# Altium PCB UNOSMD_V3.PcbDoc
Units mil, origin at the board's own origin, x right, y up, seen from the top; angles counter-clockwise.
Board outline 2700 x 2100 mil, 2 copper layers (Top, Bottom); 72 components, 62 nets, 275 pads, 97 vias.
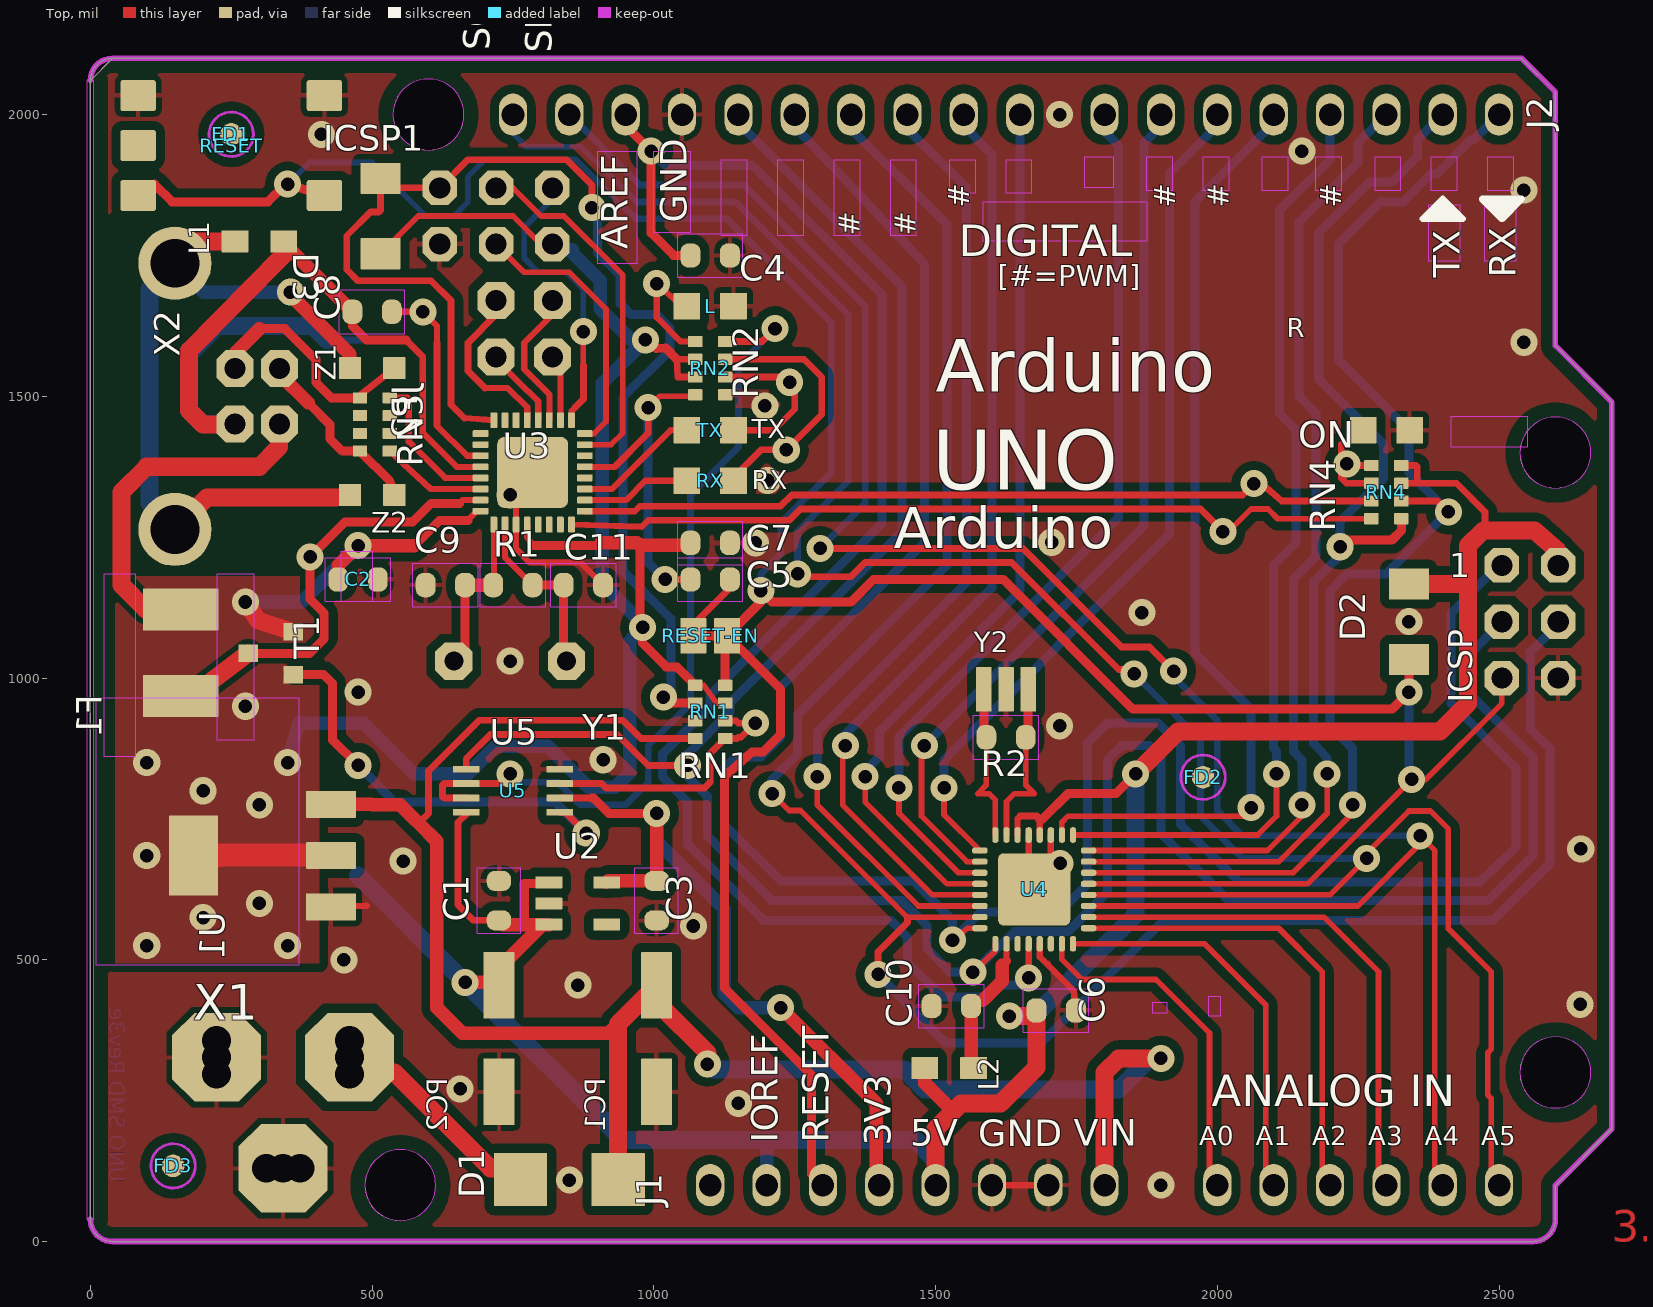
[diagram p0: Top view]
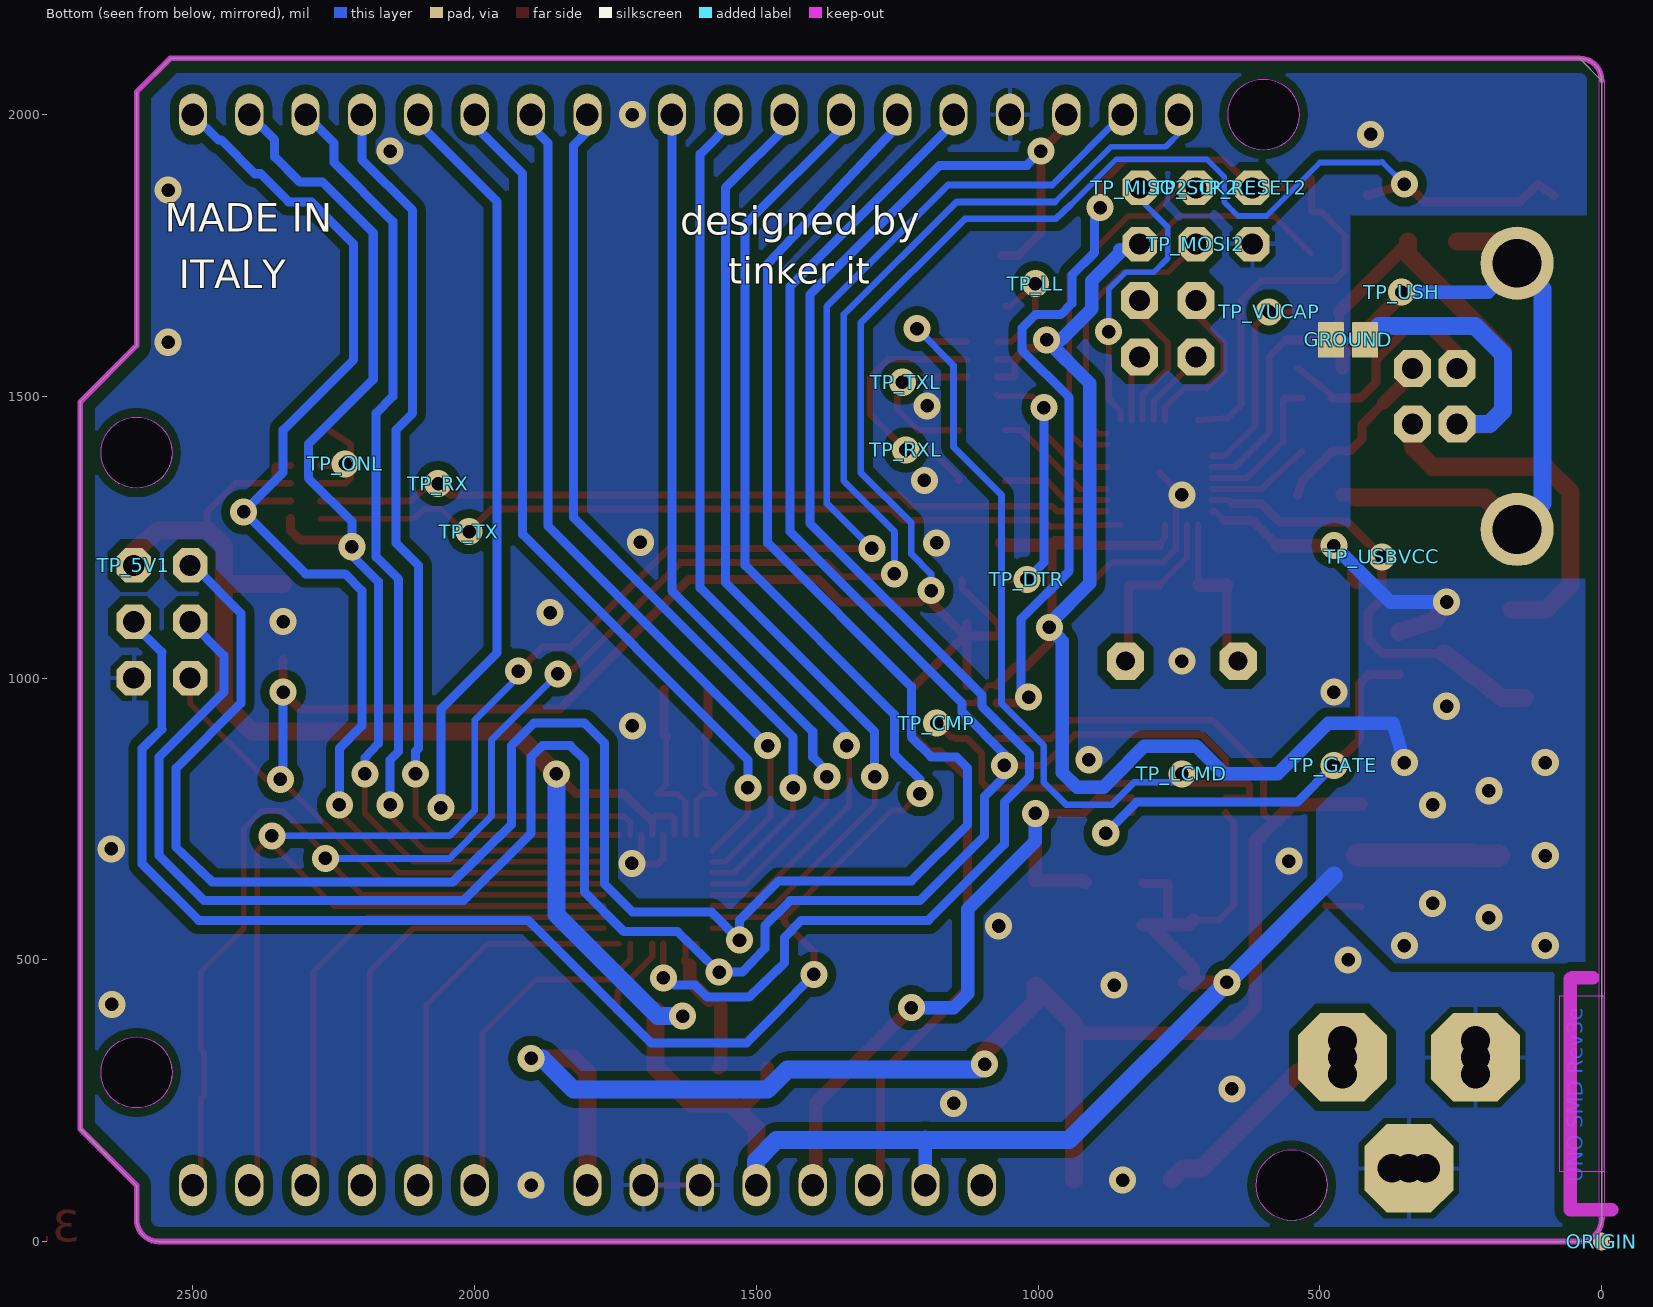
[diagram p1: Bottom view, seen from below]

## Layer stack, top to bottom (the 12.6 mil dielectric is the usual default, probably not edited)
Top Solder: solder mask 0.4, Solder Resist, Dk 3.5
Top: signal copper 1.378
Dielectric 1: dielectric 12.6, FR-4, Dk 4.8
Bottom: signal copper 1.378
Bottom Solder: solder mask 0.4, Solder Resist, Dk 3.5

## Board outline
0,2060.63 cw(c39.37,2060.63) 39.37,2100 2540,2100 2600,2040 2600,1590 2700,1490 2700,200 2600,100 2600,39.37 cw(c2560.63,39.37) 2560.63,0 39.37,0 cw(c39.37,39.37) 0,2060.63 cw(c39.37,2060.63)
cut-out: 600,1937.01 ccw(c600,2000) 662.99,2000 ccw(c600,2000) 600,2062.99 ccw(c600,2000) 537.01,2000 ccw(c600,2000)
cut-out: 550,37.01 ccw(c550,100) 612.99,100 ccw(c550,100) 550,162.99 ccw(c550,100) 487.01,100 ccw(c550,100)
cut-out: 2600,237.01 ccw(c2600,300) 2662.99,300 ccw(c2600,300) 2600,362.99 ccw(c2600,300) 2537.01,300 ccw(c2600,300)
cut-out: 2600,1337.01 ccw(c2600,1400) 2662.99,1400 ccw(c2600,1400) 2600,1462.99 ccw(c2600,1400) 2537.01,1400 ccw(c2600,1400)
cut-out: 3.83,2063.83 5.41,2060 5.41,40 3.83,36.17 0,34.59 -3.83,36.17 -5.41,40 -5.41,2060 -3.83,2063.83 0,2065.41

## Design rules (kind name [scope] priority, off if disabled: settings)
BoardOutlineClearance mdCopperDimension [All] p1: gap=10 ignorepadtopadclearanceinfootprint=FALSE except(0: Arc-SplitContinuation Track-SplitContinuation SMDPad-SplitContinuation THPad-SplitContinuation Via-SplitContinuation Fill-SplitContinuation Poly-SplitContinuation Region-SplitContinuation Text-SplitContinuation; 26: Poly-OutlineEdge Poly-CavityEdge Poly-CutoutEdge Poly-SplitBarrior)
Clearance Clearance_for_PolygonClass_Isolate_16 [InPolygonClass('Isolate_16') vs IsArc Or IsTrack Or IsPad Or IsVia Or IsFill Or IsRegion Or IsText] p1: gap=16 ignorepadtopadclearanceinfootprint=FALSE
Clearance "Clearance (Same Net)" [All] p2: gap=10 ignorepadtopadclearanceinfootprint=FALSE except(8: SMDPad-SMDPad SMDPad-THPad SMDPad-Via)
Clearance Clearance_for_NetClass_aref [InNetClass('aref') vs InNetClass('aref')] p3: gap=10 ignorepadtopadclearanceinfootprint=FALSE
Clearance Clearance_for_NetClass_usbvcc [InNetClass('usbvcc') vs InNetClass('usbvcc')] p4: gap=10 ignorepadtopadclearanceinfootprint=FALSE
Clearance Clearance_for_NetClass_gnd [InNetClass('gnd') vs InNetClass('gnd')] p5: gap=10 ignorepadtopadclearanceinfootprint=FALSE
Clearance Clearance_for_NetClass_power [InNetClass('power') vs InNetClass('power')] p6: gap=10 ignorepadtopadclearanceinfootprint=FALSE
Clearance [All] p7: gap=10 ignorepadtopadclearanceinfootprint=FALSE except(12: THPad-Via Via-Via)
HoleSize HoleSize_For_NetClass_aref [InNetClass('aref')] p1: absolutevalues=TRUE maxlimit=24 minlimit=24 maxpercent=80.000 minpercent=20.000
HoleSize HoleSize_For_NetClass_usbvcc [InNetClass('usbvcc')] p2: absolutevalues=TRUE maxlimit=24 minlimit=24 maxpercent=80.000 minpercent=20.000
HoleSize HoleSize_For_NetClass_gnd [InNetClass('gnd')] p3: absolutevalues=TRUE maxlimit=22 minlimit=22 maxpercent=80.000 minpercent=20.000
HoleSize HoleSize_For_NetClass_power [InNetClass('power')] p4: absolutevalues=TRUE maxlimit=24 minlimit=24 maxpercent=80.000 minpercent=20.000
HoleSize [All] p5: absolutevalues=TRUE maxlimit=100000 minlimit=22 maxpercent=80.000 minpercent=20.000
HoleToHoleClearance mdDrill [All] p1: gap=12 allowstackedmicrovias=TRUE
MinimumSolderMaskSliver [All] p1 off: minsoldermaskwidth=10
PasteMaskExpansion Expansion_SMDPaste_OFF [InPadClass('SMDPaste_OFF')] p1: expansion=0
PasteMaskExpansion mlMinCreamFrame [All] p2: expansion=-2
PolygonConnect PolygonConnect_For_PolygonThermal_ON_Width80000_Gap100000 [InPolygonClass('PolygonThermal_ON_Width80000_Gap100000') vs Not IsVia] p1: connectstyle=Relief reliefconductorwidth=8 reliefentries=4 polygonreliefangle="90 Angle" airgapwidth=10
PolygonConnect PolygonConnect_For_PolygonThermal_OFF [InPolygonClass('PolygonThermal_OFF')] p2: connectstyle=Direct reliefconductorwidth=10 reliefentries=4 polygonreliefangle="90 Angle" airgapwidth=10
PolygonConnect ThermalVias [IsVia] p3: connectstyle=Direct reliefconductorwidth=10 reliefentries=4 polygonreliefangle="90 Angle" airgapwidth=10
PolygonConnect [All] p4: connectstyle=Relief reliefconductorwidth=10 reliefentries=4 polygonreliefangle="90 Angle" airgapwidth=10
RoutingVias [All] p1: holewidth=22 width=46 viastyle="Through Hole" minholewidth=22 minwidth=46 maxholewidth=100 maxwidth=100
SolderMaskExpansion Expansion_SMDSolder_OFF [InPadClass('SMDSolder_OFF')] p1: expansion=0 istentingtop=FALSE
SolderMaskExpansion mlMinStopFrame [All] p2: expansion=1 istentingtop=FALSE
Width Width_For_NetClass_aref [InNetClass('aref')] p1: maxlimit=32 minlimit=10 preferedwidth=16
Width Width_For_NetClass_usbvcc [InNetClass('usbvcc')] p2: maxlimit=40 minlimit=10 preferedwidth=20
Width Width_For_NetClass_gnd [InNetClass('gnd')] p3: maxlimit=24 minlimit=10 preferedwidth=12
Width Width_For_NetClass_power [InNetClass('power')] p4: maxlimit=48 minlimit=10 preferedwidth=24
Width [All] p5: maxlimit=10000 minlimit=10 preferedwidth=10
26 further rules are at their usual default settings.

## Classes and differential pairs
polygon class PolygonThermal_ON_Width80000_Gap100000: Polygon_1_Net_GND Polygon_2_Net_GND
polygon class PolygonThermal_OFF: Polygon_1_Net_+5V Polygon_2_Net_+5V
polygon class Isolate_16: Polygon_1_Net_+5V Polygon_1_Net_GND Polygon_2_Net_GND
pad class SMDSolder_OFF: U3-1 U3-2 U3-3 U3-4 U3-5 U3-6 U3-7 U3-8 U3-9 U3-10 U3-11 U3-12 U3-13 U3-14 U3-15 U3-16 U3-17 U3-18 U3-19 U3-20 U3-21 U3-22 U3-23 U3-24 U3-25 U3-26 U3-27 U3-28 U3-29 U3-30 U3-31 U3-32 U3-EXP U4-33
pad class SMDPaste_OFF: FD1-P$1 FD2-P$1 FD3-P$1 ORIGIN-X RESET-5 TP_5V1-X TP_CMP-X TP_DTR-X TP_GATE-X TP_LCMD-X TP_LL-X TP_MISO2-X TP_MOSI2-X TP_ONL-X TP_RESET2-X TP_RX-X TP_RXL-X TP_SCK2-X TP_TX-X TP_TXL-X TP_USBVCC-X TP_USH-X TP_VUCAP-X U3-1 U3-2 U3-3 U3-4 U3-5 U3-6 U3-7 U3-8 U3-9 U3-10 U3-11 U3-12 U3-13 U3-14 U3-15 U3-16 U3-17 U3-18 U3-19 U3-20 U3-21 U3-22 U3-23 U3-24 U3-25 U3-26 U3-27 U3-28 U3-29 U3-30 U3-31 U3-32 U3-EXP U4-33
net class aref: AREF
net class usbvcc: +5V N$4 USBVCC XUSB
net class gnd: GND UGND USHIELD
net class power: PWRIN VIN

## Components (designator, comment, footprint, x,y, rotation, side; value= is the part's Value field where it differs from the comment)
C1 "100n" C0603-ROUND 725,605 r270 top
C2 "100n" C0603-ROUND 475,1175 r180 top
C3 "1u" C0603-ROUND 1005,605 r90 top
C4 "100n" C0603-ROUND 1100,1750 r180 top
C5 "100n" C0603-ROUND 1100,1175 r0 top
C6 "100n" C0603-ROUND 1714,410 r180 top
C7 "100n" C0603-ROUND 1100,1240 r0 top
C8 "1u" C0603-ROUND 500,1650 r180 top
C9 "22p" C0603-ROUND 630,1165 r180 top
C10 "100nF" C0603-ROUND 1528,418 r180 top
C11 "22p" C0603-ROUND 875,1165 r0 top
D1 "M7" SMB 850,110 r180 top
D2 "CD1206-S01575" MINIMELF 2340,1100 r270 top
D3 "CD1206-S01575" MINIMELF 515,1820 r90 top
F1 "MF-MSMF050-2 500mA" L1812 160,1045 r90 top
FD1 "" FD-1-1.5 250,1965 r0 top
FD2 "" FD-1-1.5 1974.69,824.09 r0 top
FD3 "" FD-1-1.5 146.85,134.25 r0 top
FRAME1 "" FRAME -846.46,-177.17 r0 top
GROUND "" SJ 450,1600 r180 bottom
ICSP "3x2 M" 2X03 2555,1100 r270 top
ICSP1 "3x2 M" 2X03 720,1820 r180 top
J1 "-" 1X14-CUSTOM 1800,100 r0 top
J2 "-" 1X18-CUSTOM 1800,2000 r180 top
JP2 "2x2 M-NM" 2X02 770,1620 r90 top
L "YELLOW" CHIP-LED0805 1100,1660 r270 top
L1 "BLM21" 0805 300,1775 r180 top
L2 "10uH" 0805 1524,308 r0 top
ON "GREEN" CHIP-LED0805 2300,1440 r270 top
ORIGIN "" TP-SP 0,0 r0 top
PC1 "47u" PANASONIC_D 1005,360 r90 top
PC2 "47u" PANASONIC_D 725,360 r90 top
R1 "1M" R0603-ROUND 750,1165 r0 top
R2 "1M" R0603-ROUND 1625,895 r180 top
RESET "TS42031-160R-TR-7260" TS42 250,1945 r0 top
RESET-EN "" SJ 1100,1075 r0 top
RN1 "10K" CAY16 1100,940 r90 top
RN2 "1K" CAY16 1100,1550 r270 top
RN3 "22R" CAY16 505,1450 r90 top
RN4 "1K" CAY16 2300,1330 r90 top
RX "YELLOW" CHIP-LED0805 1100,1350 r90 top
T1 "FDN340P" SOT-23 320,1045 r270 top
TP_5V1 "" TP-SP 2605,1200 r0 top
TP_CMP "" TP-SP 1180,920 r0 top
TP_DTR "" TP-SP 1020,1175 r0 top
TP_GATE "" TP-SP 475,845 r0 top
TP_LCMD "" TP-SP 745,830 r0 top
TP_LL "" TP-SP 1005,1700 r0 top
TP_MISO2 "" TP-SP 820,1870 r0 top
TP_MOSI2 "" TP-SP 720,1770 r0 top
TP_ONL "" TP-SP 2230,1380 r0 top
TP_RESET2 "" TP-SP 620,1870 r0 top
TP_RX "" TP-SP 2065,1345 r0 top
TP_RXL "" TP-SP 1235,1405 r0 top
TP_SCK2 "" TP-SP 720,1870 r0 top
TP_TX "" TP-SP 2010,1260 r0 top
TP_TXL "" TP-SP 1235,1525 r0 top
TP_USBVCC "" TP-SP 390,1215 r0 top
TP_USH "" TP-SP 355,1685 r0 top
TP_VUCAP "" TP-SP 590,1650 r0 top
TX "YELLOW" CHIP-LED0805 1100,1440 r90 top
U1 "NCP1117ST50T3G" SOT223 305,685 r90 top
U2 "LP2985-33DBVR" SOT23-DBV 865,600 r270 top
U3 "16U2" ATMEL_QFN32 785,1365 r90 top
U4 "" MLF32 1675,625 r270 top
U5 "LMV358IDGKR" MSOP08 750,800 r90 top
X1 "POWERSUPPLY_DC21MMX" POWERSUPPLY_DC-21MM 210,330 r90 top
X2 "USB-B_TH" PN61729 150,1500 r270 top
Y1 "16MHz" QS 745,1030 r180 top
Y2 "CSTCE16M0V53-R0 16MHZ" RESONATOR 1625,980 r0 top
Z1 "CG0603MLC-05E" CT/CN0603 500,1550 r180 top
Z2 "CG0603MLC-05E" CT/CN0603 500,1325 r180 top

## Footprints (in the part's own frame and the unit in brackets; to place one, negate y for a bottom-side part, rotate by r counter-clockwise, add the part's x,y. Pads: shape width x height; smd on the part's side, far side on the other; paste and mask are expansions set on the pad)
1X14-CUSTOM [mil] "1X14-CUSTOM"
  oval 50x75 hole 40: 1(-700,0) 2(-600,0) 3(-500,0) 4(-400,0) 5(-300,0) 6(-200,0) 7(-100,0) 8(0,0) 9(200,0) 10(300,0) 11(400,0) 12(500,0) 13(600,0) 14(700,0)
1X18-CUSTOM [mil] "1X18-CUSTOM"
  oval 50x75 hole 40: 1(-700,0) 2(-600,0) 3(-500,0) 4(-400,0) 5(-300,0) 6(-200,0) 7(-100,0) 8(0,0) 9(150,0) 10(250,0) 11(350,0) 12(450,0) 13(550,0) 14(650,0) 15(750,0) 16(850,0) 17(950,0) 18(1050,0)
2X02 [mil] "2X02"
  oct 66x66 / inner round 60.98 / far side oct 66x66 hole 37.4: 1(-50,-50) 2(-50,50) 3(50,-50) 4(50,50)
2X03 [mil] "2X03"
  oct 61.02x61.02 / inner round 56.38 / far side oct 61.02x61.02 hole 37.4: 1(-100,-50) 2(-100,50) 3(0,-50) 4(0,50) 5(100,-50) 6(100,50)
0805 [mm] "0805"
  rrect5% 1.2x1 smd: 1(-1.1,0) 2(1.1,0)
ATMEL_QFN32 [mil] "ATMEL_QFN32"
  rrect30% 28x12 smd paste-14 mask-14: 1(-92.55,68.9) 2(-92.55,49.21) 3(-92.55,29.53) 4(-92.55,9.84) 5(-92.55,-9.84) 6(-92.55,-29.53) 7(-92.55,-49.21) 8(-92.55,-68.9) 17(92.55,-68.9) 18(92.55,-49.21) 19(92.55,-29.53) 20(92.55,-9.84) 21(92.55,9.84) 22(92.55,29.53) 23(92.55,49.21) 24(92.55,68.9)
  rrect30% 12x28 smd paste-14 mask-14: 9(-68.9,-92.55) 10(-49.21,-92.55) 11(-29.53,-92.55) 12(-9.84,-92.55) 13(9.84,-92.55) 14(29.53,-92.55) 15(49.21,-92.55) 16(68.9,-92.55) 25(68.9,92.55) 26(49.21,92.55) 27(29.53,92.55) 28(9.84,92.55) 29(-9.84,92.55) 30(-29.53,92.55) 31(-49.21,92.55) 32(-68.9,92.55)
  rrect20% 125.98x125.98 smd paste-62.99 mask-62.99: EXP(0,0)
C0603-ROUND [mil] "C0603-ROUND"
  rrect80% 35.37x43.31 smd: 1(-35,0) 2(35,0)
  Top keep-out lines w2: 57.99,-38.7 -57.99,-38.7 -57.99,38.7 57.99,38.7 57.99,-38.7
CAY16 [mm] "CAY16"
  rrect10% 0.5x0.65 smd: 1(-1.2,-0.675) 2(-0.4,-0.675) 3(0.4,-0.675) 4(1.2,-0.675) 5(1.2,0.675) 6(0.4,0.675) 7(-0.4,0.675) 8(-1.2,0.675)
CHIP-LED0805 [mil] "CHIP-LED0805"
  rrect4% 47.24x47.24 smd: A(0,-41.34) C(0,41.34)
CT/CN0603 [mm] "CT/CN0603"
  rrect5% 1x1 smd: 1(-1,0) 2(1,0)
FD-1-1.5 [mil] "FD-1-1.5"
  rrect100% 40x40 smd paste-20: P$1(0,0)
  Top keep-out circle w5: c0,0 r39.37
FRAME [mil] "FRAME"
L1812 [mil] "L1812"
  rrect2% 74.8x133.86 smd: 1(-76.77,0) 2(76.77,0)
MINIMELF [mil] "MINIMELF"
  rrect3% 55.12x70.87 smd: A(66.93,0) C(-66.93,0)
MLF32 [mil] "MLF32"
  rrect80% 27.56x11.02 smd: 1(-96.46,68.9) 2(-96.46,49.21) 3(-96.46,29.53) 4(-96.46,9.84) 5(-96.46,-9.84) 6(-96.46,-29.53) 7(-96.46,-49.21) 8(-96.46,-68.9) 17(96.46,-68.9) 18(96.46,-49.21) 19(96.46,-29.53) 20(96.46,-9.84) 21(96.46,9.84) 22(96.46,29.53) 23(96.46,49.21) 24(96.46,68.9)
  rrect80% 11.02x27.56 smd: 9(-68.9,-96.46) 10(-49.21,-96.46) 11(-29.53,-96.46) 12(-9.84,-96.46) 13(9.84,-96.46) 14(29.53,-96.46) 15(49.21,-96.46) 16(68.9,-96.46) 25(68.9,96.46) 26(49.21,96.46) 27(29.53,96.46) 28(9.84,96.46) 29(-9.84,96.46) 30(-29.53,96.46) 31(-49.21,96.46) 32(-68.9,96.46)
  rrect15% 128.11x128.11 smd paste-64.06 mask-64.06: 33(0,0)
MSOP08 [mil] "MSOP08"
  rrect16% 11.81x47.24 smd: 1(-38.43,-83.19) 2(-12.83,-83.19) 3(12.76,-83.19) 4(38.35,-83.19) 5(38.35,83.15) 6(12.76,83.15) 7(-12.83,83.15) 8(-38.43,83.15)
PANASONIC_D [mm] "PANASONIC_D"
  rrect3% 3x1.4 smd: +(2.4,0) -(-2.4,0)
PN61729 [mil] "PN61729"
  oct 66x66 / inner round 60.98 / far side oct 66x66 hole 37.4: 1(49.21,185.43) 2(-49.21,185.43) 3(-49.21,106.69) 4(49.21,106.69)
  round 129.91 hole 86.61: P$1(-236.22,0) P$2(236.22,0)
POWERSUPPLY_DC-21MM [mil] "POWERSUPPLY_DC-21MM"
  oct 157.48x157.48 / inner round 145.49 / far side oct 157.48x157.48 hole 51.18: 1(-200,-132) 2(-3,-250) 3(-3,-14)
  round 76.77 hole 51.18: 4(-200,-162) 5(-200,-102) 6(-33,-14) 7(27,-14) 8(-33,-250) 9(27,-250)
QS [mil] "QS"
  oct 66x66 / inner round 60.98 / far side oct 66x66 hole 33.46: 1(-100,0) 2(100,0)
R0603-ROUND [mil] "R0603-ROUND"
  rrect80% 35.37x43.31 smd: 1(-35,0) 2(35,0)
  Top keep-out lines w2: -57.99,-38.7 -57.99,38.7 57.99,38.7 57.99,-38.7 -57.99,-38.7
RESONATOR [mm] "RESONATOR"
  rrect7% 0.7x2 smd: 1(-1,0) 2(0,0) 3(1,0)
SJ [mil] "SJ"
  rrect4% 46x63 smd: 1(-30,0) 2(30,0)
SMB [mil] "SMB"
  rrect2% 94.49x94.49 smd: A(86.61,0) C(-86.61,0)
SOT23-DBV [mil] "SOT23-DBV"
  rrect9% 21.65x47.24 smd: 1(-37.4,-51.18) 2(0,-51.18) 3(37.4,-51.18) 4(37.4,51.18) 5(-37.4,51.18)
SOT223 [mil] "SOT223"
  rrect4% 48x88 smd: 1(-91,-122) 2(0,-122) 3(91,-122)
  rrect2% 141.73x86.61 smd: 4(0,122.01)
SOT-23 [mil] "SOT-23"
  rrect6% 31x35 smd: 1(1,-40) 2(-37,40) 3(39,40)
TP-SP [mil] "TP-SP"
  rrect100% 31.5x31.5 smd far side paste-15.75: X(0,0)
TS42 [mil] "TS42"
  rrect15% 62.99x55.12 smd: 1(-165.35,88.58) 2(165.35,88.58) 3(-165.35,-88.58) 4(165.35,-88.58)
  rrect15% 62.99x55.12 smd paste-31.5: 5(-165.35,0)

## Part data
C1 C2 C3 C4 C5 C6 C7 C8 C9 C10 C11: library part C0603-ROUND
D1: library part SMB
D2 D3: library part MINIMELF
F1: library part L1812
FD1 FD2 FD3: library part FD-1-1.5
FRAME1: library part FRAME
GROUND RESET-EN: library part SJ
ICSP ICSP1: library part 2X03
J1: library part 1X14-CUSTOM
J2: library part 1X18-CUSTOM
JP2: library part 2X02
L ON RX TX: library part CHIP-LED0805
L1 L2: library part 0805
ORIGIN TP_5V1 TP_CMP TP_DTR TP_GATE TP_LCMD TP_LL TP_MISO2 TP_MOSI2 TP_ONL TP_RESET2 TP_RX TP_RXL TP_SCK2 TP_TX TP_TXL TP_USBVCC TP_USH TP_VUCAP: library part TP-SP
PC1 PC2: library part PANASONIC_D
R1 R2: library part R0603-ROUND
RESET: library part TS42
RN1 RN2 RN3 RN4: library part CAY16
T1: library part SOT-23
U1: library part SOT223
U2: library part SOT23-DBV
U3: library part ATMEL_QFN32
U4: library part MLF32
U5: library part MSOP08
X1: library part POWERSUPPLY_DC-21MM
X2: library part PN61729
Y1: library part QS
Y2: library part RESONATOR
Z1 Z2: library part CT/CN0603

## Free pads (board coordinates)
  round 125.98 hole 125.98 unplated: MH1(2600,1400) MH2(2600,300) MH3(600,2000) MH4(550,100)

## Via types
v1: diameter 48/48 (per signal layer), hole 24, Top to Bottom, 97 vias

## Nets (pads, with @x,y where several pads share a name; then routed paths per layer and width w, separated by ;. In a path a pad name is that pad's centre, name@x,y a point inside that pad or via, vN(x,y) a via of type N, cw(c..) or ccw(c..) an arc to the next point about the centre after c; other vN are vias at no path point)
5-GND: RESET.5
+3V3: C3.2 J1.4 U2.5 U5.2 | length 1260.5
  Top w12: U5.2 890.2,787.17
  Top w16: 890.2,787.17 892.83,787.17 920,760 v1(1005,760)
  Top w24: U2.5 918.78,640 C3.2 v1(1005,760) ; v1(1225,415) 1395,245 1395,105 J1.4
  Bottom w24: v1(1005,760) 1005,710 1125,590 1125,440 1150,415 v1(1225,415)
+5V: C1.2 C2.2 C6.2 C7.1 D2.C D3.C ICSP1.2 ICSP.2 J1.2 J1.5 L2.1 PC2.+ RN1.3 RN1.5 RN2.2 RN2.3 RN4.3 RN4.4 T1.2 TP_5V1.X U1.2 U1.4 U2.1 U2.3 U3.4 U3.32 U4.4 U4.6 U5.8 | length 9012.6
  Top w10: D3.C 581.93,1820 750,1820 800,1770 ICSP1.2 ; RN1.5@1075.67,985 RN1.5 1088.76,987.24 1111.25,955.75 RN1.3
  Top w11: 670,1280 686.1,1296.1 U3.32 ; U3.4 775.16,1249.84 785,1235 ; U4.6 1645.47,750.47 1650,755 ; U4.4 1684.84,750.16
  Top w12: U5.8 668.43,760 652.5,744.07 652.5,597.5 680,570 C1.2 ; RN2.3 1042.24,1534.25 1040.75,1565.75 RN2.2 ; 1650,755 1680,755 1684.84,750.16 ; RN4.3 2355,1345.75 ; RN4.4 2352.76,1377.24 2355,1375 2355,1345.75 ; 2475,1262 2475,1295 2424.25,1345.75 2355,1345.75
  Top w16: 575,1235 620,1280 670,1280 ; 770,562.6 770,635 811.42,635 U2.1 ; 785,1235 901.07,1235 906.61,1240.54 ; 975,1235.54 975,1110 v1(980,1090) 980,1061.93 1021.93,1020 1040.67,1020 RN1.5 ; v1(985,1600) 1005,1585 1020.75,1585.75 1040.75,1565.75 ; 1684.84,750.16 1690.16,750.16 1735,795 1820,795 v1(1855,830)
  Top w20: U1.2 U1.2@434,686 ; ICSP.2@2600,1200 ICSP.2
  Top w24: C2.2@435,1170 C2.2 440,1200 v1(475,1235) 575,1235 ; v1(665,460) PC2.+@725,460 ; C1.2 732.4,562.6 770,562.6 U2.3@802.6,562.6 ; U2.3 U2.3@802.6,562.6 ; 906.61,1240.54 970,1240.54 975,1235.54 1060.54,1235.54 C7.1 ; L2.1 1480.69,281.31 1531,231 ; PC2.+@725,460 725,485 U2.3@802.6,562.6 ; PC2.+@725,460 PC2.+ 739.49,460 PC2.+@725,460
  Top w32: v1(275,1135) 298,1102 T1.2 ; J1.5 1500,200 1531,231 1545,245 1615,245 1679,309 C6.2 1669,400 v1(1631,400) ; v1(1855,830) 1930,905 2395,905 2445,955 2445,1160 ; D2.C 2438.07,1166.93 2445,1160 ; ICSP.2@2605,1198.54 ICSP.2 2605,1225 2563,1262 2475,1262 2472,1262 2445,1235 2445,1160
  Top w40: U1.4 230,685 231,686 U1.2@434,686
  Bottom w24: v1(275,1135) 375,1135 v1(475,1235) ; v1(350,850) 370,920 485,920 575,830 670,830 719,879 812,879 841,850 840,850 884,806 931,806 957,832 957,1065 v1(980,1090) 980,1096.6 908.3,1168.3 908.3,1523.3 v1(985,1600) 960,1600 905,1655 905,1705 855,1755 855,1760 830,1760 ICSP1.2 ; J1.2 1200,180 1200,185 1205,180
  Bottom w32: 475,650 v1(665,460) 945,180 1200,180 1205,180 1464,180 1501,143 J1.5 ; v1(1631,400) 1675,400 1855,580 v1(1855,830)
  other v1: 100,525 350,525 200,575 300,600 100,685 300,775 200,800 100,850 275,950
A0: J1.9 U4.23 | length 618.5
  Top w10: U4.23 1724.21,500.79 1760,465 1891,465 1986,370 1986,118 J1.9
A1: J1.10 U4.24 | length 711.9
  Top w10: U4.24 1977.46,528.54 2086,420 2086,118 J1.10
A2: J1.11 U4.25 | length 830.3
  Top w10: U4.25 2108.9,556.1 2186,479 2186,118 J1.11
A3: J1.12 U4.26 | length 938.4
  Top w10: U4.26 2189.21,575.79 2286,479 2286,118 J1.12
A4/SDA: J1.13 J2.17 U4.27 | length 3796.6
  Top w10: U4.27 2249.47,595.47 2360,706 v1(2360,720) 2386,694 2386,118 J1.13
  Top w12: v1(1295,1230) 1655,1230 1830,1055 1880,1055 v1(1922.5,1012.5) v1@1930,1010
  Bottom w12: J2.17 975,1875 1160,1875 1375,1660 1375,1310 v1(1295,1230) ; v1(1922.5,1012.5) 1925,1010 1925,1000 2000,925 2000,765 2045,720 v1(2360,720)
A5/SCL: J1.14 J2.18 U4.28 | length 3974.1
  Top w10: U4.28 2200.16,615.16 v1(2265,680) 2272,687 2272,696 2340,764 2378,764 2410,732 2410,555 2486,479 2486,341 2480,335 2480,260 2486,254 2486,118 J1.14
  Top w12: v1(1255,1185) 1255,1180 1350,1180 1375,1205 1635,1205 1825,1015 1845,1015 v1(1852.5,1007.5)
  Bottom w10: J2.18 748.03,1998.03 748.03,1968.5 773.54,1943 871,1943 970,1845
  Bottom w12: 970,1845 1145,1845 1345,1645 1345,1350 1255,1260 v1(1255,1185) ; v1(1852.5,1007.5) 1970,890 1970,755 2045,680 v1(2265,680)
AREF: C4.2 J2.16 U4.20 | length 2810.4
  Top w10: J2.16@940,1990 J2.16
  Top w11: v1@1665.16,475.16 U4.20
  Top w12: v1(1665,468) v1@1665.16,475.16
  Top w16: J2.16@940,1990 v1(995,1935) 995,1790 1035,1750 C4.2
  Bottom w16: v1(995,1935) 1020,1910 1175,1910 1405,1680 1405,1275 1100,970 1100,950 1015,865 1015,825 1060,780 1060,705 1195,570 1420,570 1450,540 1450,495 1513,434 1588,434 1609,455 1645,455 v1(1665,468)
CMP: RN1.1 RN1.2 TP_CMP.X U5.3 | length 482.8
  Top w12: U5.3 907.24,812.76 915,805 1090,805 1100,815 1100,866.18 RN1.1 1147.76,892.76 1150,895 1155,895 v1(1180,920) 1150,920 1145.75,924.25 RN1.2
D+: RN3.5 X2.3 Z1.1 | length 426.7
  Top w12: RN3.5 476.18,1500 Z1.1
  Top w16: 300,1620 345,1620 400,1565 400,1525 427.76,1497.24 RN3.5
  Top w24: X2.3 256.69,1576.69 300,1620
  Bottom w24: X2.3@255.91,1550 X2.3
D-: RN3.8 X2.2 Z2.1 | length 325.3
  Top w16: 386.54,1488.46 425,1450 425,1425 447.24,1402.76 RN3.8 531.18,1350 Z2.1
  Top w24: X2.2 335.79,1539.21 386.54,1488.46
  Bottom w12: X2.2@335,1549.65 X2.2
DTR: C5.1 RN2.4 TP_DTR.X U3.13 | length 637.7
  Top w10: v1(990,1480) 1010,1500 RN2.4@1070.67,1500
  Top w11: U3.13 929.84,1374.84
  Top w12: 929.84,1374.84 990,1435 v1(990,1480) ; v1(1020,1175) C5.1 ; RN2.4@1070.67,1500 RN2.4
  Bottom w16: v1(990,1480) 990,1205 v1(1020,1175)
GATE_CMD: T1.3 TP_GATE.X U5.1 | length 756.9
  Top w12: U5.1 843.43,761.57 v1(880,725)
  Top w16: T1.3 414,1006 430,990 430,890 v1(475,845)
  Bottom w16: v1(475,845) 540,780 825,780 v1(880,725)
GND: C1.1 C2.1 C3.1 C4.1 C6.1 C7.2 C9.2 C10.2 C11.2 GROUND.1 ICSP1.6 ICSP.6 J1.6 J1.7 J2.15 L.C ON.C PC1.- PC2.- RESET.1 RESET.2 RN1.7 RN2.5 U1.1 U2.2 U3.3 U3.EXP U4.3 U4.5 U4.21 U5.4 X1.1 X1.3 X1.4 X1.5 X1.6 X1.7 Y2.2 | length 870.4
  Top w11: v1(745,1325) 755.47,1314.53 U3.3 755.47,1229.53 780,1205 870,1205 C11.2 ; 1665.16,679.84 U4.5 ; U4.21 1684.84,505.16 1745,445 ; v1@1704.53,687.47 U4.3
  Top w12: U1.1 490,596 ; U3.EXP@755.47,1319.53 v1(745,1325) U3.EXP ; J1.6 J1.7 ; 1665.16,679.84 1675,670 1720,670 v1(1721,671) v1@1704.53,687.47 ; 1745,445 C6.1
  Bottom w12: 425,1600 GROUND.1
  other v1: 1900,100 850,109 1150,245 656,271 2644,421 865,455 450,500 1070,560 555,675 2645,697 910,855 1720,915 475,975 745,1030 2340,1100 1866,1116 1180,1240 1706,1241 1202,1351 1197,1483 2544,1596 2544,1866 2150,1935 410,1965 1720,2000
IO0: J2.1 RN4.2 U4.30 | length 2219.2
  Top w10: U4.30 2134.53,654.53 2240,760 v1(2240,775)
  Top w12: RN4.2 2390.75,1314.25 v1(2410,1295)
  Bottom w16: v1(2240,775) 2240,875 2200,915 2200,1155 2230,1185 2300,1185 v1(2410,1295) 2340,1365 2340,1440 2215,1565 2215,1770 2290,1845 2330,1845 2380,1895 2390,1895 2450,1955 2455,1955 J2.1
IO1: J2.2 RN4.1 U4.31 | length 2064.7
  Top w10: U4.31 2109.21,674.21 2195,760 v1(2195,830)
  Top w16: v1(2218,1233) 2230,1245 2310,1245 2326.57,1261.57 RN4.1
  Bottom w16: v1(2195,830) 2195,858 2171,884 2171,1171 2220,1220 2220,1225 v1(2218,1233) 2218,1278 2295,1355 2295,1415 2180,1530 2180,1790 2270,1880 2310,1880 2355,1925 2355,1955 J2.2
IO2: J2.3 U4.32 | length 1748.3
  Top w10: U4.32 2088.9,693.9 2150,755 v1(2150,775)
  Bottom w16: v1(2150,775) 2150,855 2135,870 2135,1175 2175,1215 2175,1470 2145,1500 2145,1810 2250,1915 2250,1950 J2.3
IO3: J2.4 U4.1 | length 1688.3
  Top w10: U4.1 2071.46,721.46 2105,755 v1(2105,830)
  Bottom w16: v1(2105,830) 2105,870 2100,875 2100,1200 2140,1240 2140,1440 2110,1470 2110,1830 2200,1920 J2.4
IO4: J2.5 U4.2 | length 1697.2
  Top w10: U4.2 1724.21,744.21 1735,755 2045,755 v1(2060,770)
  Bottom w16: v1(2060,770) 2060,945 1960,1045 1960,1845 2095,1980 J2.5
IO5: J2.6 U4.9 | length 1533.3
  Top w10: v1(1515,805) 1515,757.44 U4.9
  Bottom w16: v1(1515,805) 1515,855 1915,1255 1915,1895 2000,1980 J2.6
IO6: J2.7 U4.10 | length 1558
  Top w10: v1(1480,880) 1475,875 1475,755 1555.79,674.21 U4.10
  Bottom w16: v1(1480,880) 1870,1270 1870,1950 1900,1980 J2.7
IO7: J2.8 U4.11 | length 1599.1
  Top w10: v1(1435,805) 1435,760 1540.47,654.53 U4.11
  Bottom w16: v1(1435,805) 1435,895 1825,1285 1825,1945 1800,1970 J2.8
IO8: J2.9 U4.12 | length 1597.6
  Top w10: v1(1375,825) 1375,780 1520.16,634.84 U4.12
  Bottom w10: J2.9@1650,1990 J2.9
  Bottom w16: v1(1375,825) 1375,835 1400,860 1400,905 1650,1155 J2.9@1650,1990
IO9: J2.10 U4.13 | length 1673.5
  Top w10: v1(1340,880) 1340,875 1335,870 1335,775 1494.84,615.16 U4.13
  Bottom w10: J2.10@1540,1990 J2.10
  Bottom w16: v1(1340,880) 1340,900 1600,1160 1600,1930 J2.10@1540,1990
L13: RN2.8 TP_LCMD.X U5.6 U5.7 | length 1471.7
  Top w12: U5.7 627.83,787.17 625,790 625,810 627.76,812.76 U5.6 727.76,812.76 v1(745,830) ; RN2.8 1192.24,1597.24 v1(1215,1620)
  Bottom w12: v1(745,830) 760,815 830,815 870,775 950,775 990,815 990,880 1065,955 1065,1325 1150,1410 1150,1555 v1(1215,1620)
M8RXD: RN4.7 TP_RX.X U3.9 | length 1427.5
  Top w11: U3.9 966.1,1296.1 975,1305
  Top w12: 975,1305 1225,1305 1245,1325 2045,1325 v1(2065,1345) 2078.5,1345 2114.25,1314.25 RN4.7
M8TXD: RN4.8 TP_TX.X U3.8 | length 1472.9
  Top w10: v1(2010,1260) 2020,1260 2060,1300 2090,1300 2107.24,1282.76 RN4.8
  Top w11: U3.8 978.54,1268.54 990,1280
  Top w12: 990,1280 1240,1280 1260,1300 1970,1300 v1(2010,1260)
MISO: ICSP.1 J2.13 U4.16 | length 4215.7
  Top w10: v1(1530,535) 1556.1,556.1 U4.16
  Bottom w10: J2.13@1240,1990 J2.13
  Bottom w16: J2.13@1240,1990 1480,1735 1480,1240 1225,985 1225,895 1190,860 1145,860 1125,840 1125,740 1225,640 1460,640 1530,570 v1(1530,535) 1580,585 1720,585 1770,635 1770,885 1805,920 1895,920 1935,880 1935,740 2039,638 2466,638 2530,700 2530,840 2415,955 2415,1115 2498.03,1198.03 ICSP.1
MISO2: ICSP1.1 TP_MISO2.X U3.17 | length 514.7
  Top w10: 875,1555 v1(875,1615)
  Top w11: U3.17 853.9,1473.9 860,1480
  Top w12: 860,1480 875,1495 875,1555
  Bottom w10: ICSP1.1 820,1850 770,1800 770,1745 795,1720 845,1720 875,1690 v1(875,1615)
MOSI: ICSP.4 J2.12 U4.15 | length 3836
  Top w10: v1(1210,795) 1240,765 1260,765 1449.21,575.79 ; 1450,575 1449.21,575.79 ; U4.15 1449.21,575.79
  Top w12: v1(1398,474) 1398,514 1450,566 1450,575
  Bottom w10: J2.12@1340,1985 1340,1990 J2.12
  Bottom w15: 2555,909 2555,1046
  Bottom w16: v1(1210,795) 1210,820 1255,865 1255,935 1520,1200 1520,1805 J2.12@1340,1985 ; v1(1398,474) 1465,405 1518,352 1687,352 1905,570 2490,570 2590,670 2590,875 2555,909 ; 2555,1046 2605.51,1095.51 ICSP.4
MOSI2: ICSP1.4 TP_MOSI2.X U3.16 | length 488.8
  Top w10: ICSP1.4 770,1720 850,1720 915,1655 915,1455 893.9,1433.9 U3.16
N$1: L.A RN2.1 TP_LL.X | length 215
  Top w11: L.A 1050,1660 v1(1005,1700) 1005,1640 1047.76,1597.24 RN2.1
N$3: ON.A RN4.5 RN4.6 TP_ONL.X | length 221.2
  Top w12: ON.A 2220,1415 v1@2220,1390 ; RN4.6 2229.25,1345.75 2220,1355 v1@2220,1390 ; RN4.5 2242.76,1377.24 v1(2230,1380) v1@2220,1390
N$4: C10.1 L2.2 U4.18 | length 254.8
  Top w10: 1625.79,497.79 U4.18
  Top w16: C10.1 1573,428 1584,428 ; 1618,490 1625.79,497.79
  Top w24: C10.1 1563,312.31 L2.2 ; 1584,428 1618,462 1618,490
N$35: RN2.7 RX.A TP_RXL.X | length 461.7
  Top w12: RN2.7 1266.25,1565.75 1298,1534 1298,1468 v1(1235,1405) 1190,1405 1140,1355 1140,1350 RX.A
N$36: RN2.6 TP_TXL.X TX.A | length 297.6
  Top w12: RN2.6 1225.75,1534.25 v1(1241,1525) 1250,1510 1250,1477 1212.76,1439.76 1151.57,1439.76 TX.A
  Bottom w16: TP_TXL.X v1(1241,1525)
PB4: JP2.1 U3.18 | length 118.3
  Top w11: U3.18 JP2.1@834.21,1555.79
  Top w12: JP2.1 JP2.1@834.21,1555.79
PB5: JP2.3 U3.19 | length 251.6
  Top w11: U3.19 814.53,1503.47 770,1548 770,1595 JP2.3@820,1645
  Top w12: JP2.3@820,1645 JP2.3
PB6: JP2.2 U3.20 | length 144
  Top w11: JP2.2 720,1564 794.84,1491.16 U3.20
PB7: JP2.4 U3.21 | length 300.4
  Top w11: 700,1515 740,1515 775.16,1480.84 U3.21
  Top w12: 700,1515 670,1545 670,1595 720,1645 JP2.4
PWRIN: D1.A X1.2 X1.8 X1.9 | length 396.1
  Top w32: X1.2 487,300 540,300 710,130 743.39,130 D1.A
  Bottom w32: X1.2 X1.9@462,325
RD+: RN3.4 U3.29 | length 263.7
  Top w11: 565,1420 629.84,1355.16 U3.29
  Top w12: RN3.4 562.76,1497.24 565,1495 565,1420
RD-: RN3.1 U3.30 | length 188.5
  Top w10: RN3.1 RN3.1@532.72,1402.76
  Top w11: RN3.1 603.86,1335.47 U3.30
RESET: C5.2 D2.A ICSP.5 J1.3 RESET-EN.1 RESET-EN.2 RESET.3 RESET.4 RN1.4 U4.29 | length 6074.7
  Top w10: U4.29 2159.84,634.84 v1(2345,820) 2370,820 2505,955 ICSP.5
  Top w12: RESET-EN.1 1070,1095 1135,1160 C5.2
  Top w16: RESET.3 113.58,1876.42 145,1845 315,1845 345,1875 v1(350,1876.42) RESET.4 ; RESET-EN.1 RESET-EN.2@1126.57,1075 ; RN1.4 RESET-EN.2@1126.57,1075 ; J1.3 1280,120 1280,295 1125,450 1125,825 1174,869 1194,869 1225,900 1225,980 RESET-EN.2 ; D2.A v1(2340,975) 2310,945 1850,945 1620,1175 1390,1175 1350,1135 1210,1135 v1(1190,1155) 1190,1135 RESET-EN.2 ; RESET-EN.2@1126.57,1075 1126.57,1096.57 RESET-EN.2 ; RESET-EN.2@1126.57,1075 RESET-EN.2
  Bottom w10: v1(350,1876.42) 389.58,1916 395.58,1915 500,1915 595,1820 645,1820 670,1845 670,1890 701,1921 861,1921 942,1840
  Bottom w12: 942,1840 969,1815 1130,1815 1315,1630 1315,1365 1225,1275 1225,1220 1190,1185 v1(1190,1155)
  Bottom w16: v1(2340,975) 2340,825 v1(2345,820)
RESET2: D3.A ICSP1.5 RN1.6 TP_RESET2.X U3.24 | length 2224.8
  Top w11: 663.54,1461.46 U3.24
  Top w12: 663.54,1461.46 640,1485 640,1670 605,1705 475,1705 455,1725 455,1785 496.93,1826.93 511.93,1826.93 515,1830 D3.A 531.93,1870 ICSP1.5 670,1920 845,1920 890,1875 v1(890,1835)
  Top w16: v1(1017,966) 1017.25,965.75 1030,955 1030.75,955.75 RN1.6
  Bottom w16: v1(890,1835) 900,1825 900,1755 940,1715 940,1665 960,1645 1005,1645 1029,1621 1029,1582 945,1498 945,1190 1030,1105 1030,979 v1(1017,966)
RXLED: RX.C U3.10 | length 195.3
  Top w11: U3.10 950.79,1315.79 985,1350 RX.C
SCK: ICSP.3 J2.14 U4.17 U5.5 | length 4709.8
  Top w10: v1(1566,478) 1606.1,516.1 U4.17
  Top w12: U5.5 666.85,856.85 710,900 935,900 990,845 v1(1060,845)
  Bottom w10: J2.14@1140,1995 1145,1995 J2.14
  Bottom w16: J2.14@1140,1995 1440,1695 1440,1260 1135,955 1135,940 1060,865 v1(1060,845) 1060,825 1095,790 1095,720 1210,605 1440,605 1485,560 1485,520 1525,478 v1(1566,478) 1640,550 1735,550 1805,620 1805,855 1830,880 1880,880 1900,860 1900,725 2020,605 2480,605 2560,685 2560,860 2445,975 2445,1040 ICSP.3
SCK2: ICSP1.3 TP_SCK2.X U3.15 | length 645.3
  Top w10: ICSP1.3 750,1870 800,1820 840,1820 945,1715 945,1435 924.21,1414.21 U3.15
SS: J2.11 U4.14 | length 1749.4
  Top w10: v1(1290,825) 1290,775 1469.53,595.47 U4.14
  Bottom w10: J2.11@1440,1985 1440,1990 J2.11
  Bottom w16: v1(1290,825) 1290,905 1555,1170 1555,1870 J2.11@1440,1985
TP_VUCAP: C8.1 TP_VUCAP.X U3.27 | length 367
  Top w11: C8.1 v1(590,1650) 615,1625 615,1595 ; 615,1448 668.47,1394.53 U3.27
  Top w12: 615,1448 615,1595
TXLED: TX.C U3.11 | length 224.4
  Top w11: U3.11 925.47,1335.47 1030,1440 TX.C
UGND: C8.2 GROUND.2 L1.1 U3.28 X2.4 | length 1541.4
  Top w11: 590,1435 650.16,1374.84 U3.28
  Top w12: 560,1600 590,1570 590,1435
  Top w16: C8.2 465,1625 490,1600 560,1600
  Top w24: L1.1 343.31,1771.69 343.46,1771.54 C8.2
  Top w32: X2.4 255.91,1450 200,1450 175,1475 175,1581 344.31,1752.31 343.46,1771.54 L1.1
  Bottom w24: X2.4@255.91,1450 X2.4
  Bottom w32: X2.4 199.21,1450.79 175,1475 175,1575 225,1625 395,1625 GROUND.2
USBVCC: F1.1 T1.1 TP_USBVCC.X U3.31 | length 838.6
  Top w11: 655,1310 660.79,1315.79 U3.31
  Top w16: T1.1 389,1044 415,1070 415,1115 390,1140 v1(390,1215) 452,1277 572,1277 605,1310 655,1310
  Top w24: F1.1@136.77,965 F1.1
  Top w32: F1.1@136.77,965 176,965 T1.1
USHIELD: L1.2 TP_USH.X X2.P$1 X2.P$2 Z1.2 Z2.2 | length 1373.4
  Top w24: v1(355,1685) 355,1680 460.63,1574.37 Z1.2 ; 435.63,1320.63 440.63,1320.63 445,1325 Z2.2
  Top w32: X2.P$2 206.85,1320.63 435.63,1320.63 ; X2.P$1 188.78,1775 L1.2
  Bottom w24: X2.P$1 201.22,1685 v1(355,1685)
  Bottom w32: X2.P$2 150,1265 105,1310 105,1690 150,1735 X2.P$1
VIN: D1.C J1.8 PC1.+ RN1.8 U1.3 | length 3250.1
  Top w12: 582.5,742.5 600,760 600,835 690,925 945,925 977.24,892.76 RN1.8
  Top w24: U1.3 498.76,776 550,774.76 ; 500,775 550,774.76 ; 942.76,392.24 936.61,386.09 920.51,370 660,370 615,415 615,710 582.5,742.5 575,750 550,774.76 ; PC1.+ PC1.+@1005.51,450
  Top w32: D1.C 936.61,386.09 942.76,392.24 PC1.+ 1005,425 1095,335 v1(1095,315) ; J1.8 1800,300 1825,325 v1(1900,325)
  Bottom w32: v1(1095,315) 1105,305 1445,305 1480,270 1825,270 1880,325 v1(1900,325)
XT1: C9.1 R1.1 U3.1 Y1.2 | length 315.2
  Top w10: R1.1 R1.1@720,1170
  Top w11: R1.1@716.1,1171.1 U3.1
  Top w12: R1.1 R1.1@716.1,1171.1
  Top w16: Y1.2 650,1050 665,1050 C9.1
  Top w24: C9.1 R1.1
XT2: C11.1 R1.2 U3.2 Y1.1 | length 319.9
  Top w11: U3.2 735.79,1214.21 R1.2
  Top w16: R1.2 C11.1 840,1055 845,1050 Y1.1
XTAL1: R2.1 U4.7 Y2.3 | length 307.4
  Top w10: U4.7 1625.79,780.79 1640,795 1675,795 1660,810 R2.1
  Top w16: R2.1 1664.37,899.37 Y2.3
XTAL2: R2.2 U4.8 Y2.1 | length 291.2
  Top w10: R2.2 1590,810 1575,795 1595,795 1606.1,783.9 U4.8
  Top w16: Y2.1 1585.63,899.37 R2.2
XUSB: F1.2 X2.1 | length 642.5
  Top w32: F1.2 98.23,1121.77 55,1165 55,1330 100,1375 300,1375 335,1410 X2.1
  Bottom w12: X2.1@335,1450.35 X2.1
pads on no net: FD1.P$1 FD2.P$1 FD3.P$1 J1.1 ORIGIN.X RN3.2 RN3.3 RN3.6 RN3.7 U2.4 U3.5 U3.6 U3.7 U3.12 U3.14 U3.22 U3.23 U3.25 U3.26 U4.19 U4.22 U4.33

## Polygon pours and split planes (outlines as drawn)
GND on Bottom "Polygon_1_Net_GND" (solid, remove dead copper, pour order 2): 21,2079 2666.66,2079 2679,2066.66 2679,21 33.34,21 21,33.34 21,1189 446,1189 446,1821 21,1821
+5V on Bottom "Polygon_1_Net_+5V" (solid, remove dead copper, pour order 1): 29,1176 431,1176 431,842.49 506,767.49 506,632.51 367.49,494 29,494
GND on Top "Polygon_2_Net_GND" (solid, remove dead copper, pour order 3): 21,2079 2679,2079 2679,21 21.02,21 15.98,1204 446,1204 446,1821 21,1821
+5V on Top "Polygon_2_Net_+5V" (solid, remove dead copper, pour order 0): 44,494 44,1181 406,1181 406,494

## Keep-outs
Top:
  region: 10,490 10,965 370,965 370,490
  region: 1625,1860 1625,1920 1670,1920 1670,1860
  region: 2480,1865 2480,1925 2525,1925 2525,1865
  region: 2380,1865 2380,1925 2425,1925 2425,1865
  region: 2280,1865 2280,1925 2325,1925 2325,1865
  region: 2175,1865 2175,1925 2220,1925 2220,1865
  region: 2080,1865 2080,1925 2125,1925 2125,1865
  region: 1975,1865 1975,1925 2020,1925 2020,1865
  region: 1875,1865 1875,1925 1920,1925 1920,1865
  region: 1765,1870 1765,1925 1815,1925 1815,1870
  region: 445,1135 445,1225 500,1225 500,1135
  region: 1985,400 1985,435 2005,435 2005,400
  region: 1885,405 1885,425 1910,425 1910,405
  region: 225,890 225,1185 290,1185 290,890
  region: 25,860 25,1185 80,1185 80,860
  region: 2415,1410 2415,1465 2550,1465 2550,1410
  region: 2475,1740 2475,1840 2530,1840 2530,1740
  region: 2375,1740 2375,1840 2430,1840 2430,1740
  region: 1585,1775 1585,1845 1875,1845 1875,1775
  region: 1525,1860 1525,1920 1570,1920 1570,1860
  region: 1420,1785 1420,1920 1465,1920 1465,1785
  region: 1320,1785 1320,1920 1365,1920 1365,1785
  region: 1220,1785 1220,1920 1265,1920 1265,1785
  region: 1120,1785 1120,1920 1165,1920 1165,1785
  region: 1000,1790 1000,1935 1065,1935 1065,1790
  region: 900,1735 900,1935 970,1935 970,1735
Bottom:
  region: -5,125 -5,435 75,435 75,125
  lines w24: -18,56 56,56 56,466 52,466 52,468 16,468
Keep-Out Layer:
  lines w10: 0,39.37 ccw(c39.37,39.37) 39.37,0 2560.63,0 ccw(c2560.63,39.37) 2600,39.37 2600,100 2700,200 2700,1490 2600,1590 2600,2040 2540,2100 39.37,2100 ccw(c39.37,2060.63) 0,2060.63

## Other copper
Top:
  text "3.325" at 2700,0 h56.1
Bottom:
  text "UNO SMD Rev3e" at 33.81,105.58 h27.2 r270

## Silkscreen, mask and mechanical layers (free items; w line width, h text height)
Top Overlay:
  lines w12: 2380,1820 2400,1840 2420,1820 2390,1820 2405,1830 ; 2485,1845 2525,1845 2505,1825 2490,1840 2510,1840 ; 2505,1830 2505,1835 ; 2365,1815 2400,1850 2435,1815 2365,1815 ; 2470,1850 2505,1815 2540,1850 2470,1850
  text "SCL" at 708.83,2114.48 h47.6 r90
  text "SDA" at 818.83,2109.48 h47.6 r90
  text "#" at 1560,1835 h37.4 r90
  text "#" at 1925,1835 h37.4 r90
  text "#" at 2020,1835 h37.4 r90
  text "#" at 2220,1835 h37.4 r90
  text "GND" at 1058.33,1807.63 h47.6 r90
  text "#" at 1365,1785 h37.4 r90
  text "#" at 1465,1785 h37.4 r90
  text "AREF" at 953.75,1761.04 h47.6 r90
  text "DIGITAL" at 1541.43,1748.59 h56.1
  text "TX" at 2429.83,1710.48 h47.6 r90
  text "RX" at 2530,1710 h47.6 r90
  text "[#=PWM]" at 1610,1695 h37.4
  text "R" at 2123,1605 h34
  text "Arduino" at 1500,1508 h93.5
  text "RN2" at 1200.79,1496.06 h77.5 r90
  text "TX" at 1173.35,1426.01 h34
  text "RX" at 1173.35,1335.01 h34
  text "UNO" at 1494,1334 h106.25
  text "RN4" at 2224.41,1259.84 h77.5 r90
  text "Arduino" at 1426,1230 h73.1
  text "1" at 2411.28,1178.91 h42.5
  text "U5" at 708.66,866.14 h77.5
  text "RN1" at 1043.31,807.09 h77.5
  text "ANALOG IN" at 1990,240 h56.1
  text "IOREF" at 1220,175 h47.6 r90
  text "RESET" at 1310,175 h47.6 r90
  text "3V3" at 1420,170 h47.6 r90
  text "5V" at 1455,170 h47.6
  text "VIN" at 1745,170 h47.6
  text "A0" at 1968.06,170.48 h34
  text "A1" at 2068.06,170.48 h34
  text "A2" at 2168.06,170.48 h34
  text "A3" at 2268.06,170.48 h34
  text "A4" at 2368.06,170.48 h34
  text "A5" at 2468.06,170.48 h34
  text "GND" at 1575.33,169.48 h47.6
Bottom Overlay:
  text "MADE IN" at 2550,1775 h86.8
  text "designed by" at 1635,1770 h86.8
  text "tinker it" at 1550,1700 h47.6
  text "ITALY" at 2525,1675 h86.8
Top Paste:
  circle w12: c720,1570 r26
  circle w12: c820,1570 r26
  circle w12: c820,1670 r26
  circle w12: c720,1670 r26
Dimension:
  lines w10: 0,39.37 ccw(c39.37,39.37) 39.37,0 2560.63,0 ccw(c2560.63,39.37) 2600,39.37 2600,100 2700,200 2700,1490 2600,1590 2600,2040 2540,2100 39.37,2100 ccw(c39.37,2060.63) 0,2060.63 ; 0,40 0,2060
tPlace:
  circle w10: c870,1920 r10
  lines w12: 1150,1820 1195,1775 1515,1775 ; 1935,1775 2255,1775 2300,1820
  text "1" at 2417.58,1914.14 h47.6 r90
  text "9" at 1557.58,1898.28 h47.6 r90
  text "8" at 1657.58,1898.28 h47.6 r90
  text "7" at 1817.58,1898.28 h47.6 r90
  text "6" at 1917.58,1898.28 h47.6 r90
  text "5" at 2017.58,1898.28 h47.6 r90
  text "4" at 2117.58,1898.28 h47.6 r90
  text "3" at 2217.58,1898.28 h47.6 r90
  text "2" at 2317.58,1898.28 h47.6 r90
  text "0" at 2517.58,1898.28 h47.6 r90
  text "11" at 1357.58,1874.48 h47.6 r90
  text "13" at 1157.58,1858.62 h47.6 r90
  text "12" at 1257.58,1858.62 h47.6 r90
  text "10" at 1457.58,1858.62 h47.6 r90
  text "ITALY" at 1879,1109 h59.5
  text "MADE IN" at 1425,1108 h59.5
ReferenceLC:
  text "L" at 1165,1640 h77.5
  text "TX" at 1155,1420 h62
  text "ON" at 2155,1410 h77.5
  text "RX" at 1159,1329 h62
  text "PC1" at 697,330 h49.6
  text "PC2" at 976,323 h49.6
